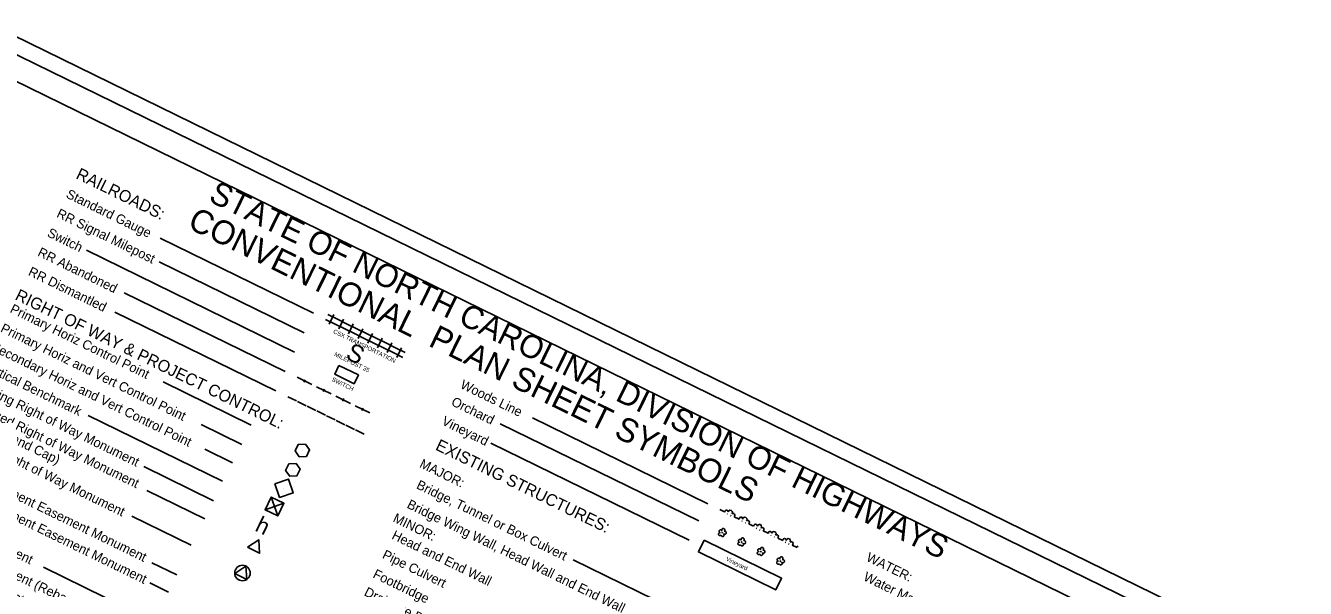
# Model space of a CAD drawing. Extents: x 1517888 to 1526099, y 633375 to 640181.
# Drawn here: x 1523591 to 1525964, y 636868 to 637911 of the extents above; entities that cross this region are included whole.
import ezdxf

# ---------------------------------------------------------------- set-up
doc = ezdxf.new("R2010")
doc.units = 0
doc.layers.add('Default', color=7, linetype='Continuous')
doc.layers.add('Sheet Plot Border Outside CELL', color=7, linetype='Continuous')

msp = doc.modelspace()

# ---------------------------------------------------------------- linework, layer by layer
at = {"layer": 'Default'}
for p, q in [((1525946.6, 636729.5), (1522921, 638209.2)), ((1525847.2, 636695.4), (1522955.1, 638109.8)), ((1524125, 637377.8), (1523840.5, 637516.9)), ((1524089.8, 637306), (1523703.9, 637494.7)), ((1524107.4, 637341.9), (1523838.9, 637473.2)), ((1524072.3, 637270.1), (1523773.9, 637416)), ((1524054.7, 637234.1), (1523756.3, 637380.1)), ((1524054.7, 637234.1), (1523756.3, 637380.1)), ((1524147, 637366.5), (1524165, 637357.7)), ((1524151.4, 637375.5), (1524169.3, 637366.7)), ((1524153.8, 637357.6), (1524162.6, 637375.6)), ((1524169.3, 637366.7), (1524187.3, 637357.9)), ((1524171.7, 637348.8), (1524180.5, 637366.8)), ((1524165, 637357.7), (1524182.9, 637348.9)), ((1524182.9, 637348.9), (1524200.9, 637340.1)), ((1524187.3, 637357.9), (1524205.3, 637349.1)), ((1524189.7, 637340), (1524198.5, 637358)), ((1524200.9, 637340.1), (1524218.8, 637331.4)), ((1524205.3, 637349.1), (1524223.2, 637340.3)), ((1524207.7, 637331.3), (1524216.4, 637349.2)), ((1524223.2, 637340.3), (1524241.2, 637331.6)), ((1524225.6, 637322.5), (1524234.4, 637340.4)), ((1524218.8, 637331.4), (1524236.8, 637322.6)), ((1524236.8, 637322.6), (1524254.7, 637313.8)), ((1524241.2, 637331.6), (1524259.1, 637322.8)), ((1524243.6, 637313.7), (1524252.3, 637331.7)), ((1524259.1, 637322.8), (1524277.1, 637314)), ((1524261.5, 637304.9), (1524270.3, 637322.9)), ((1524254.7, 637313.8), (1524272.7, 637305)), ((1524272.7, 637305), (1524290.7, 637296.2)), ((1524277.1, 637314), (1524295, 637305.2)), ((1524279.5, 637296.1), (1524288.3, 637314.1)), ((1524009.5, 637170.8), (1523846, 637250.8)), ((1524094.5, 637259.2), (1524121.5, 637246)), ((1524109.1, 637254.8), (1524106.9, 637250.3)), ((1524077, 637223.3), (1524093.1, 637215.4)), ((1524130.4, 637241.6), (1524157.4, 637228.4)), ((1524145, 637237.3), (1524142.8, 637232.8)), ((1524166.3, 637224), (1524193.3, 637210.9)), ((1524094.9, 637214.5), (1524111.1, 637206.6)), ((1524112.9, 637205.7), (1524129, 637197.8)), ((1524130.8, 637196.9), (1524147, 637189)), ((1524180.9, 637219.7), (1524178.7, 637215.2)), ((1524202.3, 637206.5), (1524229.2, 637193.3)), ((1524216.8, 637202.1), (1524214.6, 637197.6)), ((1523956.4, 637066.8), (1523707.1, 637188.7)), ((1524148.8, 637188.1), (1524164.9, 637180.2)), ((1524166.7, 637179.3), (1524182.9, 637171.4)), ((1524839.2, 636993.2), (1524471.2, 637173.1)), ((1524855.9, 637024.8), (1524530.7, 637183.9)), ((1523991.9, 637134.9), (1523916.6, 637171.7)), ((1524184.7, 637170.6), (1524200.9, 637162.7)), ((1524202.6, 637161.8), (1524218.8, 637153.9)), ((1523974.5, 637100.7), (1523923.2, 637125.8)), ((1524821.6, 636957.2), (1524453.6, 637137.2)), ((1524104.2, 637123.7), (1524104.2, 637123.7)), ((1523939.4, 637030.6), (1523810, 637093.9)), ((1524086.6, 637087.8), (1524086.6, 637087.8)), ((1523923.1, 636996.8), (1523815.8, 637049.3)), ((1524070.1, 637053.5), (1524070.1, 637053.5)), ((1524052.6, 637019.8), (1524052.6, 637019.8)), ((1524878.2, 637014), (1524887.1, 637009.6)), ((1523898.1, 636948.1), (1523787.7, 637002.1)), ((1524892, 637006.1), (1524892.9, 637005.6)), ((1524898.3, 637003), (1524899.2, 637002.6)), ((1524905.1, 637000.8), (1524914.1, 636996.4)), ((1524918.9, 636992.9), (1524919.8, 636992.5)), ((1524925.2, 636989.8), (1524926.1, 636989.4)), ((1524932, 636987.6), (1524941, 636983.2)), ((1524945.9, 636979.7), (1524946.8, 636979.3)), ((1524952.2, 636976.7), (1524953.1, 636976.2)), ((1524959, 636974.4), (1524967.9, 636970.1)), ((1524972.8, 636966.6), (1524973.7, 636966.1)), ((1524979.1, 636963.5), (1524980, 636963.1)), ((1524985.9, 636961.3), (1524994.9, 636956.9)), ((1524016.9, 636945.1), (1524016.9, 636945.1)), ((1524999.7, 636953.4), (1525000.6, 636953)), ((1525006, 636950.3), (1525006.9, 636949.9)), ((1525012.8, 636948.1), (1525021.8, 636943.7)), ((1523871.3, 636892.9), (1523825, 636915.5)), ((1524758.1, 636847), (1524606.5, 636921.1)), ((1523827.5, 636807.9), (1523624.2, 636907.3)), ((1523993.1, 636896.5), (1523993.1, 636896.5)), ((1523855.8, 636861.2), (1523821.2, 636878.2))]:
    msp.add_line(p, q, dxfattribs=at)
for points in [[(1524172.1, 637281.2), (1524208, 637263.7), (1524200, 637247.3), (1524164.1, 637264.9)], [(1524079.1, 637099), (1524092.5, 637099.7), (1524100.2, 637088.8), (1524094.2, 637076.8), (1524080.7, 637075.8), (1524073.2, 637086.8)], [(1524053.3, 637061.8), (1524078.6, 637070.5), (1524087.3, 637045.1), (1524062, 637036.5)], [(1524046.6, 637037.1), (1524069.9, 637025.7), (1524058.5, 637002.4), (1524035.2, 637013.8)], [(1524002.5, 636944.2), (1524023.2, 636958.1), (1524024.9, 636933.2)], [(1523978.7, 636895.6), (1523999.5, 636909.5), (1524001.2, 636884.6)]]:
    msp.add_lwpolyline(points, close=True, dxfattribs=at)
for points in [[(1524098.4, 637111.7), (1524090.8, 637122.7), (1524096.7, 637134.7), (1524110, 637135.6), (1524117.6, 637124.6), (1524111.7, 637112.6), (1524098.4, 637111.7)], [(1524069.9, 637025.7), (1524035.2, 637013.8), (1524052.5, 637019.8), (1524058.5, 637002.4), (1524046.6, 637037.1)], [(1524052.5, 637019.8), (1524069.9, 637025.7), (1524046.6, 637037.1), (1524052.5, 637019.8)], [(1524052.5, 637019.8), (1524035.2, 637013.8), (1524058.5, 637002.4), (1524052.5, 637019.8)], [(1524886.4, 636974), (1524886.9, 636974.4), (1524887.3, 636974.9), (1524887.4, 636975.4), (1524887.6, 636976), (1524887.6, 636976.6), (1524887.5, 636977.2), (1524887.2, 636977.8), (1524886.9, 636978.2), (1524886.4, 636978.7), (1524885.9, 636979), (1524885.3, 636979.1), (1524884.7, 636979.2), (1524884.1, 636979.2), (1524883.5, 636979), (1524883, 636978.6), (1524882.6, 636978.3), (1524882.2, 636977.8), (1524882, 636977.2), (1524881.8, 636976.6), (1524881.8, 636976.1), (1524881.9, 636975.3), (1524881.6, 636975.8), (1524881.1, 636976.2), (1524880.6, 636976.5), (1524880, 636976.5), (1524879.5, 636976.5), (1524878.9, 636976.4), (1524878.4, 636976.2), (1524877.9, 636975.9), (1524877.6, 636975.5), (1524877.2, 636974.9), (1524877, 636974.4), (1524877, 636973.9), (1524877.1, 636973.2), (1524877.2, 636972.8), (1524877.5, 636972.3), (1524877.9, 636971.7), (1524878.4, 636971.4), (1524878.9, 636971.2), (1524878.4, 636971.2), (1524877.7, 636971.1), (1524877.3, 636970.8), (1524876.8, 636970.4), (1524876.4, 636969.9), (1524876.2, 636969.5), (1524876, 636968.9), (1524876.1, 636968.3), (1524876.1, 636967.7), (1524876.3, 636967.2), (1524876.6, 636966.7), (1524877, 636966.3), (1524877.5, 636966.1), (1524878, 636965.8), (1524878.5, 636965.7), (1524879.2, 636965.8), (1524879.7, 636965.8), (1524880.6, 636966.4)], [(1524880.6, 636966.4), (1524881.4, 636965.3), (1524881.8, 636964.8), (1524882.3, 636964.5), (1524882.9, 636964.3), (1524883.4, 636964.3), (1524884, 636964.3), (1524884.6, 636964.5), (1524885.1, 636964.8), (1524885.5, 636965.1), (1524886, 636965.6), (1524886.1, 636966.2), (1524886.3, 636966.8), (1524886.2, 636967.5), (1524886.1, 636968), (1524885.8, 636968.5), (1524885.4, 636969), (1524885.9, 636968.6), (1524886.5, 636968.3), (1524887, 636968.3), (1524887.7, 636968.3), (1524888.3, 636968.3), (1524888.9, 636968.6), (1524889.4, 636969), (1524889.8, 636969.5), (1524890.1, 636970), (1524890.3, 636970.6), (1524890.4, 636971.2), (1524890.2, 636971.8), (1524890, 636972.5), (1524889.7, 636973), (1524889.2, 636973.4), (1524888.7, 636973.8), (1524888.2, 636974.1), (1524887.6, 636974.1), (1524887, 636974.1), (1524886.4, 636974)], [(1524883.3, 636971.6), (1524883, 636971.7), (1524882.8, 636971.7), (1524882.6, 636971.7), (1524882.5, 636971.4), (1524882.4, 636971.2), (1524882.5, 636971), (1524882.7, 636970.8), (1524882.9, 636970.7), (1524883.2, 636970.8), (1524883.4, 636971.1), (1524883.4, 636971.3), (1524883.3, 636971.6)], [(1524922.3, 636956.4), (1524922.8, 636956.8), (1524923.2, 636957.3), (1524923.3, 636957.9), (1524923.5, 636958.5), (1524923.5, 636959), (1524923.4, 636959.6), (1524923.1, 636960.2), (1524922.8, 636960.7), (1524922.3, 636961.2), (1524921.8, 636961.4), (1524921.3, 636961.6), (1524920.6, 636961.6), (1524920.1, 636961.6), (1524919.4, 636961.5), (1524918.9, 636961.1), (1524918.5, 636960.7), (1524918.1, 636960.2), (1524917.9, 636959.7), (1524917.7, 636959.1), (1524917.8, 636958.5), (1524917.8, 636957.8), (1524917.5, 636958.3), (1524917, 636958.6), (1524916.5, 636958.9), (1524916, 636958.9), (1524915.4, 636959), (1524914.8, 636958.8), (1524914.3, 636958.6), (1524913.8, 636958.3), (1524913.5, 636957.9), (1524913.1, 636957.3), (1524912.9, 636956.8), (1524912.9, 636956.3), (1524913, 636955.7), (1524913.1, 636955.2), (1524913.5, 636954.7), (1524913.9, 636954.2), (1524914.3, 636953.9), (1524914.8, 636953.6), (1524914.3, 636953.6), (1524913.6, 636953.5), (1524913.2, 636953.3), (1524912.8, 636952.8), (1524912.3, 636952.4), (1524912.1, 636951.9), (1524911.9, 636951.3), (1524912, 636950.8), (1524912, 636950.2), (1524912.2, 636949.6), (1524912.5, 636949.2), (1524912.9, 636948.8), (1524913.4, 636948.5), (1524914, 636948.2), (1524914.4, 636948.1), (1524915.1, 636948.2), (1524915.7, 636948.3), (1524916.5, 636948.9)], [(1524849.1, 636957.1), (1524992.8, 636886.9), (1524982.2, 636865.3), (1524838.6, 636935.6), (1524849.1, 636957.1)], [(1524916.5, 636948.9), (1524917.3, 636947.7), (1524917.7, 636947.3), (1524918.2, 636946.9), (1524918.8, 636946.7), (1524919.3, 636946.7), (1524919.9, 636946.8), (1524920.5, 636946.9), (1524921, 636947.2), (1524921.4, 636947.6), (1524921.9, 636948), (1524922, 636948.6), (1524922.2, 636949.2), (1524922.1, 636949.9), (1524922, 636950.4), (1524921.7, 636950.9), (1524921.3, 636951.4), (1524921.8, 636951.1), (1524922.4, 636950.8), (1524923, 636950.7), (1524923.6, 636950.7), (1524924.2, 636950.8), (1524924.8, 636951), (1524925.3, 636951.5), (1524925.7, 636951.9), (1524926, 636952.4), (1524926.2, 636953), (1524926.3, 636953.7), (1524926.1, 636954.3), (1524925.9, 636954.9), (1524925.6, 636955.4), (1524925.2, 636955.9), (1524924.7, 636956.2), (1524924.1, 636956.5), (1524923.5, 636956.6), (1524922.9, 636956.5), (1524922.3, 636956.4)], [(1524919.2, 636954), (1524919, 636954.1), (1524918.7, 636954.1), (1524918.5, 636954.1), (1524918.4, 636953.9), (1524918.3, 636953.7), (1524918.4, 636953.4), (1524918.6, 636953.3), (1524918.8, 636953.2), (1524919.1, 636953.3), (1524919.3, 636953.5), (1524919.3, 636953.7), (1524919.2, 636954)], [(1524958.2, 636938.8), (1524958.7, 636939.2), (1524959.1, 636939.7), (1524959.3, 636940.3), (1524959.4, 636940.9), (1524959.4, 636941.5), (1524959.3, 636942.1), (1524959.1, 636942.6), (1524958.7, 636943.1), (1524958.2, 636943.6), (1524957.8, 636943.8), (1524957.2, 636944), (1524956.5, 636944.1), (1524956, 636944), (1524955.3, 636943.9), (1524954.8, 636943.5), (1524954.4, 636943.1), (1524954.1, 636942.6), (1524953.8, 636942.1), (1524953.6, 636941.5), (1524953.7, 636940.9), (1524953.8, 636940.2), (1524953.4, 636940.7), (1524952.9, 636941.1), (1524952.4, 636941.3), (1524951.9, 636941.4), (1524951.3, 636941.4), (1524950.7, 636941.3), (1524950.2, 636941.1), (1524949.7, 636940.8), (1524949.4, 636940.4), (1524949, 636939.8), (1524948.9, 636939.3), (1524948.8, 636938.7), (1524949, 636938.1), (1524949, 636937.6), (1524949.4, 636937.1), (1524949.8, 636936.6), (1524950.2, 636936.3), (1524950.7, 636936), (1524950.2, 636936.1), (1524949.6, 636935.9), (1524949.1, 636935.7), (1524948.7, 636935.3), (1524948.2, 636934.8), (1524948, 636934.4), (1524947.8, 636933.8), (1524947.9, 636933.2), (1524947.9, 636932.6), (1524948.1, 636932.1), (1524948.4, 636931.6), (1524948.8, 636931.2), (1524949.3, 636930.9), (1524949.9, 636930.7), (1524950.4, 636930.5), (1524951, 636930.7), (1524951.6, 636930.7), (1524952.4, 636931.3)], [(1524952.4, 636931.3), (1524953.2, 636930.2), (1524953.6, 636929.7), (1524954.1, 636929.4), (1524954.7, 636929.2), (1524955.2, 636929.1), (1524955.8, 636929.2), (1524956.4, 636929.3), (1524956.9, 636929.7), (1524957.3, 636930), (1524957.8, 636930.5), (1524958, 636931), (1524958.1, 636931.6), (1524958, 636932.3), (1524957.9, 636932.8), (1524957.6, 636933.3), (1524957.2, 636933.9), (1524957.7, 636933.5), (1524958.3, 636933.2), (1524958.9, 636933.2), (1524959.5, 636933.2), (1524960.1, 636933.2), (1524960.7, 636933.5), (1524961.2, 636933.9), (1524961.6, 636934.4), (1524961.9, 636934.9), (1524962.1, 636935.5), (1524962.2, 636936.1), (1524962.1, 636936.7), (1524961.8, 636937.4), (1524961.5, 636937.9), (1524961.1, 636938.3), (1524960.6, 636938.7), (1524960, 636938.9), (1524959.4, 636939), (1524958.8, 636939), (1524958.2, 636938.8)], [(1524955.1, 636936.4), (1524954.9, 636936.6), (1524954.6, 636936.6), (1524954.4, 636936.6), (1524954.3, 636936.3), (1524954.2, 636936.1), (1524954.3, 636935.8), (1524954.6, 636935.7), (1524954.7, 636935.6), (1524955, 636935.7), (1524955.2, 636935.9), (1524955.2, 636936.2), (1524955.1, 636936.4)], [(1524994.1, 636921.3), (1524994.6, 636921.7), (1524995, 636922.2), (1524995.2, 636922.7), (1524995.3, 636923.3), (1524995.3, 636923.9), (1524995.2, 636924.5), (1524995, 636925.1), (1524994.7, 636925.6), (1524994.1, 636926), (1524993.7, 636926.3), (1524993.1, 636926.4), (1524992.5, 636926.5), (1524991.9, 636926.5), (1524991.3, 636926.3), (1524990.7, 636925.9), (1524990.3, 636925.6), (1524990, 636925.1), (1524989.7, 636924.5), (1524989.5, 636923.9), (1524989.6, 636923.4), (1524989.7, 636922.7), (1524989.4, 636923.1), (1524988.9, 636923.5), (1524988.3, 636923.8), (1524987.8, 636923.8), (1524987.3, 636923.8), (1524986.6, 636923.7), (1524986.1, 636923.5), (1524985.6, 636923.2), (1524985.3, 636922.8), (1524984.9, 636922.2), (1524984.8, 636921.7), (1524984.7, 636921.2), (1524984.9, 636920.6), (1524985, 636920.1), (1524985.3, 636919.6), (1524985.7, 636919), (1524986.1, 636918.7), (1524986.6, 636918.5), (1524986.1, 636918.5), (1524985.5, 636918.4), (1524985, 636918.1), (1524984.6, 636917.7), (1524984.1, 636917.2), (1524983.9, 636916.8), (1524983.7, 636916.2), (1524983.8, 636915.6), (1524983.8, 636915), (1524984, 636914.5), (1524984.3, 636914), (1524984.7, 636913.6), (1524985.2, 636913.4), (1524985.8, 636913.1), (1524986.3, 636913), (1524986.9, 636913.1), (1524987.5, 636913.2), (1524988.3, 636913.7)], [(1524988.3, 636913.7), (1524989.1, 636912.6), (1524989.5, 636912.1), (1524990, 636911.8), (1524990.6, 636911.6), (1524991.2, 636911.6), (1524991.7, 636911.6), (1524992.4, 636911.8), (1524992.9, 636912.1), (1524993.3, 636912.4), (1524993.7, 636912.9), (1524993.9, 636913.5), (1524994, 636914.1), (1524993.9, 636914.8), (1524993.9, 636915.3), (1524993.5, 636915.8), (1524993.1, 636916.3), (1524993.6, 636915.9), (1524994.3, 636915.6), (1524994.8, 636915.6), (1524995.5, 636915.6), (1524996, 636915.6), (1524996.6, 636915.9), (1524997.1, 636916.3), (1524997.5, 636916.8), (1524997.9, 636917.3), (1524998, 636917.9), (1524998.1, 636918.5), (1524998, 636919.1), (1524997.7, 636919.8), (1524997.4, 636920.3), (1524997, 636920.8), (1524996.5, 636921.1), (1524995.9, 636921.4), (1524995.3, 636921.5), (1524994.7, 636921.4), (1524994.1, 636921.3)], [(1524991, 636918.9), (1524990.8, 636919), (1524990.6, 636919), (1524990.3, 636919), (1524990.2, 636918.7), (1524990.1, 636918.5), (1524990.2, 636918.3), (1524990.5, 636918.1), (1524990.7, 636918.1), (1524990.9, 636918.1), (1524991.1, 636918.4), (1524991.1, 636918.6), (1524991, 636918.9)]]:
    msp.add_lwpolyline(points, dxfattribs=at)
msp.add_circle((1523993.1, 636896.5), 14.4, dxfattribs=at)
for centre, radius, start, end in [((1524890.6, 637010.1), 3.16, 352.3727, 193.1692), ((1524897.8, 637008.8), 4.12, 319.9015, 167.974), ((1524903.2, 637004), 3.16, 294.7062, 135.5028), ((1524917.6, 636997), 3.16, 352.3727, 193.1692), ((1524924.7, 636995.7), 4.12, 319.9015, 167.974), ((1524930.1, 636990.8), 3.16, 294.7062, 135.5028), ((1524944.5, 636983.8), 3.16, 352.3727, 193.1692), ((1524951.7, 636982.5), 4.12, 319.9015, 167.974), ((1524957.1, 636977.6), 3.16, 294.7062, 135.5028), ((1524971.4, 636970.6), 3.16, 352.3727, 193.1692), ((1524978.6, 636969.3), 4.12, 319.9015, 167.974), ((1524984, 636964.5), 3.16, 294.7062, 135.5028), ((1524998.4, 636957.4), 3.16, 352.3727, 193.1692), ((1525005.5, 636956.2), 4.12, 319.9015, 167.974), ((1525010.9, 636951.3), 3.16, 294.7062, 135.5028), ((1525025.3, 636944.3), 3.16, 130.1887, 177.6867)]:
    msp.add_arc(centre, radius, start, end, dxfattribs=at)
at = {"layer": 'Sheet Plot Border Outside CELL'}
msp.add_lwpolyline([(1525964.3, 636688.2), (1522938.8, 638168), (1521972.2, 636191.7), (1524997.7, 634712)], close=True, dxfattribs=at)

# ---------------------------------------------------------------- texts
at = {"layer": 'Default'}
for s, height, p in [('RAILROADS:', 21.99, (1523682.6, 637628.5)), ('Standard Gauge', 17.49, (1523664.6, 637592.9)), ('STATE OF NORTH CAROLINA, DIVISION OF HIGHWAYS', 42.814, (1523928.3, 637586.4)), ('RR Signal Milepost', 17.49, (1523647, 637557)), ('CONVENTIONAL  PLAN SHEET SYMBOLS', 44.04, (1523889.2, 637536.8)), ('Switch', 17.49, (1523629.5, 637521.1)), ('RR Abandoned', 17.49, (1523611.9, 637485.1)), ('RR Dismantled', 17.49, (1523594.3, 637449.2)), ('RIGHT OF WAY & PROJECT CONTROL:', 21.988, (1523569.7, 637404)), ('Primary Horiz Control Point', 17.49, (1523560.6, 637380.2)), ('Primary Horiz and Vert Control Point', 17.49, (1523543, 637344.3)), ('CSX TRANSPORTATION', 7.996, (1524160.5, 637341.5)), ('Secondary Horiz and Vert Control Point', 17.49, (1523525.6, 637310.1)), ('S', 33, (1524182.6, 637294.8)), ('Vertical Benchmark', 17.49, (1523507.5, 637276.2)), ('MILEPOST 35', 7.996, (1524162.5, 637299.2)), ('Existing Right of Way Monument', 17.49, (1523491.6, 637242.3)), ('SWITCH', 8, (1524157.9, 637252.5)), ('Woods Line', 17.49, (1524395.6, 637239.9)), ('Proposed Right of Way Monument', 17.49, (1523474.9, 637210.5)), ('Orchard', 17.49, (1524378.8, 637208.2)), ('Proposed Right of Way Monument', 17.49, (1523448.5, 637158.1)), ('     (Rebar and Cap)', 17.49, (1523463.9, 637188.1)), ('Vineyard', 17.49, (1524361.2, 637172.3)), ('EXISTING STRUCTURES:', 21.988, (1524349.3, 637125.8)), ('Existing Permanent Easement Monument', 17.49, (1523422.1, 637106.5)), ('MAJOR:', 17.49, (1524320, 637093.2)), ('Proposed Permanent Easement Monument', 17.49, (1523406.2, 637073.7)), ('Bridge, Tunnel or Box Culvert', 17.49, (1524314.2, 637054)), ('Existing C/A Monument', 17.49, (1523379.7, 637019.5)), ('Bridge Wing Wall, Head Wall and End Wall', 17.49, (1524296.6, 637018)), ('MINOR:', 17.49, (1524270.7, 636992.4)), ('Proposed C/A Monument (Rebar and Cap)', 17.49, (1523363.3, 636986.8)), ('h', 30, (1524014.5, 636975.7)), ('Proposed C/A Monument (Concrete)', 17.49, (1523347, 636953.6)), ('Head and End Wall', 17.49, (1524268.5, 636960.6)), ('Pipe Culvert', 17.49, (1524251, 636924.7)), ('WATER:', 17.49, (1525148.4, 636919.8)), ('Vineyard', 8, (1524888.5, 636920.1)), ('Footbridge', 17.49, (1524233.5, 636888.8)), ('Water Manhole', 17.49, (1525143.2, 636883.7)), ('Drainage Box: Catch Basin, DI or JB', 17.49, (1524217.3, 636855.7))]:
    msp.add_text(s, height=height, rotation=333.9377, dxfattribs=at).set_placement(p)

doc.saveas('drawing.dxf')
